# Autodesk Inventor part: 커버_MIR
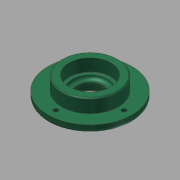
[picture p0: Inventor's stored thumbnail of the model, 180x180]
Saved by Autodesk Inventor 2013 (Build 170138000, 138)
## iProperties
Created: 2014-10
Part Number: 커버_MIR
Material: 강철, 연강
Document SubType Name: Modeling
Designer: Administrator
Mass: 351.567 g
Surface Area: 161.165 cm^2
Volume: 44.7286 cm^3
Density: 7.86 g/cm^3
Company: 한국ATC센터
Author: KYOUNG IL JANG
Revision Number: 1
d0: 80.000 mm
d1: 7.000 mm
d2: 0.00 deg
d3: 54.000 mm
d4: 13.000 mm
d5: 0.00 deg
d6: 40.000 mm
d7: 5.000 mm
d8: 0.00 deg
d11: 25.000 mm
d13: 32.000 mm
d14: 8.300 mm
d20: 34.000 mm
d22: 40.000 mm
d23: 12.000 mm
d25: 3.000 mm
d27: 0.300 mm
d28: 1.000 mm
d31: 1.200 mm
d33: 30.00 deg
d34: 3.000 mm
d35: 65.000 mm
d36: 4.500 mm
d38: 8.000 mm
d39: 4.400 mm
d43: 4.000 ul
d44: 360.00 deg
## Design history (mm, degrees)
derived "커버.ipt"
  sketch "스케치1"
    geometry: C1 r 40 at (0, 0) reference; 1 further point
  sketch "스케치2"
    geometry: C1 r 27 at (0, 0) reference; 1 further point
  sketch "스케치3"
    geometry: C1 r 20 at (0, 0) reference; 1 further point
  sketch "스케치4"
    geometry: 3 further points
    constraints: 1 horizontal alignment
feature "솔리드1::커버.ipt"
tag "피쳐 태그1"
node "솔리드1"
other parameters: "d0" = 10, "d1" = 7, "d2" = 0 deg, "d3" = 54, "d4" = 13, "d5" = 0 deg, "d6" = 40, "d7" = 5, "d8" = 0 deg, "d11" = 25, "d13" = 32, "d14" = 8.3, "d20" = 34, "d22" = 40, "d23" = 12, "d25" = 3, "d27" = 0.3, "d28" = 1, "d31" = 1.2, "d33" = 30 deg, "d34" = 3, "d35" = 65, "d36" = 4.5, "d38" = 8, "d39" = 4.4, "d43" = 4, "d44" = 360 deg
